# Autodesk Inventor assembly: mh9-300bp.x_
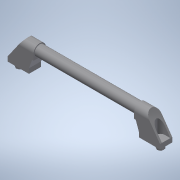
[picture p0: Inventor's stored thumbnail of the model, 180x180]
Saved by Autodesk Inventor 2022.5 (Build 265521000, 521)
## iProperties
Part Number: mh9-300bp.x_
Material: 一般
Document SubType Name: Assembly
Designer: ImaoCorp
Sending System: SOLIDWORKS 2017-2017317
MC: AMD64
MC_MODEL: Intel64 Family 6 Model 60 Stepping 3, GenuineIntel
OS: Windows_NT
FRU: Parasolid Version 29.0, build 201,  4-17-2017
FORMAT: text
GUISE: transmit
KEY: mh9-300bp
FILE: mh9-300bp.x_t
DATE: Fri Jul 26 11:47:19 2019
Author: ImaoCorp
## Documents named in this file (4)
- X:\14_SW2022-Inv2022\00_全2023-1023新製品(TCC)まで\m\mh9-300bp\MH9-300BP.iam
- X:\14_SW2022-Inv2022\00_全2023-1023新製品(TCC)まで\m\mh9-300bp\mh9-300bp_01.ipt
- X:\14_SW2022-Inv2022\00_全2023-1023新製品(TCC)まで\m\mh9-300bp\mh9-300bp_02.ipt
- X:\14_SW2022-Inv2022\00_全2023-1023新製品(TCC)まで\m\mh9-300bp\mh9-300bp_03.ipt
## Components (3 placed, 3 different names)
1. mh9-300bp_01
2. mh9-300bp_02
3. mh9-300bp_03
